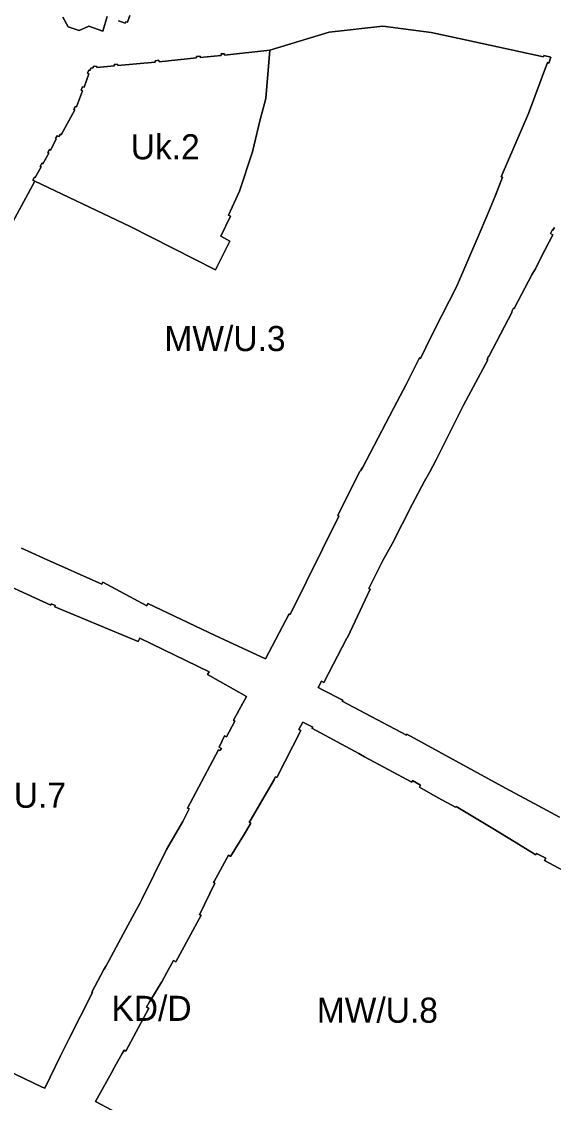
# Model space of a CAD drawing. Extents: x 7423367 to 7424726, y 5546744 to 5548391.
# Drawn here: x 7424088.2 to 7424194.2, y 5547952.8 to 5548168.2 of the extents above; entities that cross this region are included whole.
import ezdxf

# ---------------------------------------------------------------- set-up
doc = ezdxf.new("R2010")
doc.units = 0
doc.layers.add('linie_rozgraniczajace', color=7, linetype='Continuous')
doc.layers.add('oznaczenia_przeznaczen', color=7, linetype='Continuous')

msp = doc.modelspace()

# ---------------------------------------------------------------- linework, layer by layer
at = {"layer": 'linie_rozgraniczajace'}
for points in [[(7424105.26, 5548169.29), (7424104.4, 5548166.36), (7424101.64, 5548167.35), (7424099.67, 5548166.47), (7424097.5, 5548167.2), (7424096.42, 5548169.13)], [(7424096.42, 5548169.13), (7424097.5, 5548167.2), (7424099.67, 5548166.47), (7424101.64, 5548167.35), (7424104.4, 5548166.36), (7424105.26, 5548169.29)], [(7424109.76, 5548169.49), (7424109.3, 5548168.1), (7424108.95, 5548168.19), (7424108.86, 5548167.92), (7424107.5, 5548168.39)], [(7424107.5, 5548168.39), (7424108.86, 5548167.92), (7424108.95, 5548168.19), (7424109.3, 5548168.1), (7424109.76, 5548169.49)], [(7424084.67, 5548124.99), (7424090.84, 5548136.42), (7424109.83, 5548127.39), (7424126.83, 5548118.73), (7424129.73, 5548124.48), (7424127.91, 5548125.47), (7424129.81, 5548129.49), (7424129.45, 5548129.67), (7424131.65, 5548134.44), (7424134.22, 5548142.26), (7424134.55, 5548143.68), (7424135.66, 5548148.46), (7424136.87, 5548152.88), (7424137.67, 5548162.53), (7424149.49, 5548166.12), (7424160.16, 5548167.34), (7424169.79, 5548166.09), (7424175.42, 5548164.85), (7424192.21, 5548161.19), (7424192.27, 5548161.46), (7424193.68, 5548161.14), (7424193.23, 5548159.97), (7424193.01, 5548160.08), (7424189.17, 5548149.89), (7424183.78, 5548137.32), (7424184.04, 5548137.2), (7424182.59, 5548133.44), (7424180.88, 5548129.44), (7424179.35, 5548125.87), (7424174.83, 5548115.34), (7424171.94, 5548109.63), (7424169.76, 5548105.34), (7424167.69, 5548101.09), (7424167.49, 5548101.19), (7424165.03, 5548096.29), (7424164.85, 5548095.93), (7424163.04, 5548092.53), (7424156.18, 5548079.43), (7424155.73, 5548078.7), (7424155.55, 5548078.51), (7424151.21, 5548069.77), (7424151.39, 5548069.66), (7424141.7, 5548050.08), (7424141.5, 5548050.17), (7424136.82, 5548041.22), (7424126.76, 5548045.87), (7424113.37, 5548052.24), (7424113.16, 5548051.79), (7424104.39, 5548056.51), (7424104.17, 5548056.11), (7424092.55, 5548061.3), (7424090.24, 5548062.32), (7424088.17, 5548063.25)], [(7424088.17, 5548063.25), (7424090.24, 5548062.32), (7424092.55, 5548061.3), (7424104.17, 5548056.11), (7424104.39, 5548056.51), (7424113.16, 5548051.79), (7424113.37, 5548052.24), (7424126.76, 5548045.87), (7424136.82, 5548041.22), (7424141.5, 5548050.17), (7424141.7, 5548050.08), (7424151.39, 5548069.66), (7424151.21, 5548069.77), (7424155.55, 5548078.51), (7424155.73, 5548078.7), (7424156.18, 5548079.43), (7424163.04, 5548092.53), (7424164.85, 5548095.93), (7424165.03, 5548096.29), (7424167.49, 5548101.19), (7424167.69, 5548101.09), (7424169.76, 5548105.34), (7424171.94, 5548109.63), (7424174.83, 5548115.34), (7424179.35, 5548125.87), (7424180.88, 5548129.44), (7424182.59, 5548133.44), (7424184.04, 5548137.2), (7424183.78, 5548137.32), (7424189.17, 5548149.89), (7424193.01, 5548160.08), (7424193.23, 5548159.97), (7424193.68, 5548161.14), (7424192.27, 5548161.46), (7424192.21, 5548161.19), (7424175.42, 5548164.85), (7424169.79, 5548166.09), (7424160.16, 5548167.34), (7424149.49, 5548166.12), (7424137.67, 5548162.53), (7424128.64, 5548161.54), (7424128.63, 5548161.82), (7424127.96, 5548161.79), (7424127.94, 5548161.51), (7424123.79, 5548161.07), (7424123.77, 5548161.35), (7424123.09, 5548161.31), (7424123.08, 5548161.03), (7424115.62, 5548160.25), (7424115.54, 5548160.54), (7424114.84, 5548160.45), (7424114.82, 5548160.18), (7424107.37, 5548159.51), (7424107.34, 5548159.77), (7424106.67, 5548159.7), (7424106.7, 5548159.43), (7424103.2, 5548159.08), (7424103.16, 5548159.37), (7424102.45, 5548159.3), (7424102.48, 5548159.02), (7424102.02, 5548158.95), (7424101.88, 5548158.55), (7424101.58, 5548158.57), (7424101.36, 5548157.98), (7424101.6, 5548157.84), (7424100.66, 5548155.14), (7424100.35, 5548155.26), (7424100.11, 5548154.57), (7424100.33, 5548154.46), (7424100.14, 5548153.92), (7424099.17, 5548151.23), (7424098.9, 5548151.34), (7424098.6, 5548150.68), (7424098.79, 5548150.64), (7424096.12, 5548145.7), (7424095.92, 5548145.78), (7424095.68, 5548145.34), (7424095.31, 5548145.5), (7424094.96, 5548144.93), (7424095.13, 5548144.83), (7424093.98, 5548142.62), (7424093.8, 5548142.72), (7424093.45, 5548142.14), (7424093.61, 5548142.04), (7424092.44, 5548139.91), (7424092.27, 5548140), (7424091.93, 5548139.38), (7424092.1, 5548139.29), (7424090.91, 5548137.17), (7424090.76, 5548137.25), (7424090.43, 5548136.65), (7424090.84, 5548136.42), (7424084.67, 5548124.99)], [(7424195.36, 5548009.65), (7424191.2, 5548011.91), (7424184.64, 5548015.43), (7424164.97, 5548026.2), (7424164.89, 5548026.04), (7424152.1, 5548032.8), (7424152.18, 5548032.96), (7424148.13, 5548035.03), (7424147.33, 5548035.5), (7424147.98, 5548036.74), (7424148.4, 5548036.52), (7424153.04, 5548045.33), (7424153.12, 5548045.49), (7424157.63, 5548055.14), (7424157.4, 5548055.27), (7424158.82, 5548058.18), (7424160.2, 5548060.81), (7424162.06, 5548064.16), (7424166.05, 5548071.97), (7424168.46, 5548076.61), (7424169.46, 5548078.39), (7424170.8, 5548080.86), (7424176.23, 5548091.76), (7424181.11, 5548100.84), (7424180.94, 5548100.91), (7424181.25, 5548101.55), (7424181.33, 5548101.51), (7424185.96, 5548110.41), (7424185.89, 5548110.45), (7424186.23, 5548111.09), (7424186.32, 5548111.05), (7424189.95, 5548117.93), (7424190.57, 5548118.95), (7424191.81, 5548121.39), (7424194.07, 5548125.77), (7424193.58, 5548126.03), (7424193.9, 5548126.67), (7424194.01, 5548126.61), (7424194.39, 5548127.21)], [(7424194.39, 5548127.21), (7424194.01, 5548126.61), (7424193.9, 5548126.67), (7424193.58, 5548126.03), (7424194.07, 5548125.77), (7424191.81, 5548121.39), (7424190.57, 5548118.95), (7424189.95, 5548117.93), (7424186.32, 5548111.05), (7424186.23, 5548111.09), (7424185.89, 5548110.45), (7424185.96, 5548110.41), (7424181.33, 5548101.51), (7424181.25, 5548101.55), (7424180.94, 5548100.91), (7424181.11, 5548100.84), (7424176.23, 5548091.76), (7424170.8, 5548080.86), (7424169.46, 5548078.39), (7424168.46, 5548076.61), (7424166.05, 5548071.97), (7424162.06, 5548064.16), (7424160.2, 5548060.81), (7424158.82, 5548058.18), (7424157.4, 5548055.27), (7424157.63, 5548055.14), (7424153.12, 5548045.49), (7424153.04, 5548045.33), (7424148.4, 5548036.52), (7424147.98, 5548036.74), (7424147.33, 5548035.5), (7424148.13, 5548035.03), (7424152.18, 5548032.96), (7424152.1, 5548032.8), (7424164.89, 5548026.04), (7424164.97, 5548026.2), (7424184.64, 5548015.43), (7424191.2, 5548011.91), (7424195.36, 5548009.65)], [(7424067.71, 5548063.98), (7424089.25, 5548054.14), (7424094.01, 5548051.92), (7424094.13, 5548052.19), (7424094.93, 5548051.86), (7424094.83, 5548051.6), (7424111.44, 5548044.71), (7424111.76, 5548045.34), (7424125.57, 5548038.63), (7424125.27, 5548038.07), (7424133.02, 5548033.73), (7424130.41, 5548029.03), (7424130.7, 5548028.8), (7424129.06, 5548025.66), (7424128.67, 5548025.87), (7424127.58, 5548023.59), (7424128.01, 5548023.35), (7424127.74, 5548022.92), (7424127.43, 5548023.06), (7424121.29, 5548011.47), (7424121.61, 5548011.32), (7424121.48, 5548011.04), (7424120.31, 5548008.8), (7424117.11, 5548003.2), (7424112.18, 5547993.28), (7424111.83, 5547992.61), (7424110.71, 5547990.55), (7424110.31, 5547989.78), (7424107.99, 5547985.5), (7424107.52, 5547984.64), (7424105.05, 5547980.04), (7424104.6, 5547979.3), (7424102.19, 5547974.81), (7424102.31, 5547974.74), (7424097.62, 5547965.38), (7424095.94, 5547962.06), (7424092.85, 5547955.66), (7424092.48, 5547955.79), (7424092.32, 5547955.87), (7424079.83, 5547961.85)], [(7424079.83, 5547961.85), (7424092.32, 5547955.87), (7424092.48, 5547955.79), (7424092.85, 5547955.66), (7424095.94, 5547962.06), (7424097.62, 5547965.38), (7424102.31, 5547974.74), (7424102.19, 5547974.81), (7424104.6, 5547979.3), (7424105.05, 5547980.04), (7424107.52, 5547984.64), (7424107.99, 5547985.5), (7424110.31, 5547989.78), (7424110.71, 5547990.55), (7424111.83, 5547992.61), (7424112.18, 5547993.28), (7424117.11, 5548003.2), (7424120.31, 5548008.8), (7424121.48, 5548011.04), (7424121.61, 5548011.32), (7424121.29, 5548011.47), (7424127.43, 5548023.06), (7424127.74, 5548022.92), (7424128.01, 5548023.35), (7424127.58, 5548023.59), (7424128.67, 5548025.87), (7424129.06, 5548025.66), (7424130.7, 5548028.8), (7424130.41, 5548029.03), (7424133.02, 5548033.73), (7424125.27, 5548038.07), (7424125.57, 5548038.63), (7424111.76, 5548045.34), (7424111.44, 5548044.71), (7424094.83, 5548051.6), (7424094.93, 5548051.86), (7424094.13, 5548052.19), (7424094.01, 5548051.92), (7424089.25, 5548054.14), (7424067.71, 5548063.98)], [(7424112.68, 5547947.82), (7424102.94, 5547953.02), (7424103.91, 5547954.79), (7424106.11, 5547958.71), (7424106.71, 5547959.8), (7424108.24, 5547962.55), (7424108.62, 5547963.22), (7424108.95, 5547963.04), (7424113.55, 5547971.57), (7424113.09, 5547971.82), (7424113.69, 5547972.83), (7424114.47, 5547974.11), (7424115.88, 5547976.41), (7424116.15, 5547976.84), (7424117.18, 5547978.71), (7424118.48, 5547981.06), (7424118.94, 5547980.83), (7424123.96, 5547990.1), (7424123.68, 5547990.22), (7424126.7, 5547996.53), (7424126.47, 5547996.62), (7424126.58, 5547996.82), (7424129.43, 5548002.1), (7424129.84, 5548001.84), (7424132.4, 5548006.03), (7424133.87, 5548008.45), (7424133.56, 5548008.65), (7424133.74, 5548008.95), (7424138.63, 5548017.21), (7424138.56, 5548017.25), (7424138.81, 5548017.7), (7424139.06, 5548017.57), (7424143.84, 5548026.97), (7424143.47, 5548027.17), (7424144.23, 5548028.61), (7424146.21, 5548027.62), (7424146.05, 5548027.37), (7424155.38, 5548022.33), (7424156.54, 5548021.7), (7424165.93, 5548016.63), (7424166.11, 5548016.96), (7424167.67, 5548016.05), (7424167.48, 5548015.65), (7424170.17, 5548014.13), (7424171.93, 5548013.14), (7424174.69, 5548011.64), (7424174.82, 5548011.81), (7424181.77, 5548007.6), (7424185.17, 5548005.56), (7424190.64, 5548002.15), (7424190.79, 5548002.43), (7424192.65, 5548001.47), (7424192.42, 5548001.04), (7424211.72, 5547990.69)], [(7424211.72, 5547990.69), (7424192.42, 5548001.04), (7424192.65, 5548001.47), (7424190.79, 5548002.43), (7424190.64, 5548002.15), (7424185.17, 5548005.56), (7424181.77, 5548007.6), (7424174.82, 5548011.81), (7424174.69, 5548011.64), (7424171.93, 5548013.14), (7424170.17, 5548014.13), (7424167.48, 5548015.65), (7424167.67, 5548016.05), (7424166.11, 5548016.96), (7424165.93, 5548016.63), (7424156.54, 5548021.7), (7424155.38, 5548022.33), (7424146.05, 5548027.37), (7424146.21, 5548027.62), (7424144.23, 5548028.61), (7424143.47, 5548027.17), (7424143.84, 5548026.97), (7424139.06, 5548017.57), (7424138.81, 5548017.7), (7424138.56, 5548017.25), (7424138.63, 5548017.21), (7424133.74, 5548008.95), (7424133.56, 5548008.65), (7424133.87, 5548008.45), (7424132.4, 5548006.03), (7424129.84, 5548001.84), (7424129.43, 5548002.1), (7424126.58, 5547996.82), (7424126.47, 5547996.62), (7424126.7, 5547996.53), (7424123.68, 5547990.22), (7424123.96, 5547990.1), (7424118.94, 5547980.83), (7424118.48, 5547981.06), (7424117.18, 5547978.71), (7424116.15, 5547976.84), (7424115.88, 5547976.41), (7424114.47, 5547974.11), (7424113.69, 5547972.83), (7424113.09, 5547971.82), (7424113.55, 5547971.57), (7424108.95, 5547963.04), (7424108.62, 5547963.22), (7424108.24, 5547962.55), (7424106.71, 5547959.8), (7424106.11, 5547958.71), (7424103.91, 5547954.79), (7424102.94, 5547953.02), (7424112.68, 5547947.82)]]:
    msp.add_lwpolyline(points, dxfattribs=at)
msp.add_lwpolyline([(7424090.43, 5548136.65), (7424090.76, 5548137.25), (7424090.91, 5548137.17), (7424092.1, 5548139.29), (7424091.93, 5548139.38), (7424092.27, 5548140), (7424092.44, 5548139.91), (7424093.61, 5548142.04), (7424093.45, 5548142.14), (7424093.8, 5548142.72), (7424093.98, 5548142.62), (7424095.13, 5548144.83), (7424094.96, 5548144.93), (7424095.31, 5548145.5), (7424095.68, 5548145.34), (7424095.92, 5548145.78), (7424096.12, 5548145.7), (7424098.79, 5548150.64), (7424098.6, 5548150.68), (7424098.9, 5548151.34), (7424099.17, 5548151.23), (7424100.14, 5548153.92), (7424100.33, 5548154.46), (7424100.11, 5548154.57), (7424100.35, 5548155.26), (7424100.66, 5548155.14), (7424101.6, 5548157.84), (7424101.36, 5548157.98), (7424101.58, 5548158.57), (7424101.88, 5548158.55), (7424102.02, 5548158.95), (7424102.48, 5548159.02), (7424102.45, 5548159.3), (7424103.16, 5548159.37), (7424103.2, 5548159.08), (7424106.7, 5548159.43), (7424106.67, 5548159.7), (7424107.34, 5548159.77), (7424107.37, 5548159.51), (7424114.82, 5548160.18), (7424114.84, 5548160.45), (7424115.54, 5548160.54), (7424115.62, 5548160.25), (7424123.08, 5548161.03), (7424123.09, 5548161.31), (7424123.77, 5548161.35), (7424123.79, 5548161.07), (7424127.94, 5548161.51), (7424127.96, 5548161.79), (7424128.63, 5548161.82), (7424128.64, 5548161.54), (7424137.67, 5548162.53), (7424136.87, 5548152.88), (7424135.66, 5548148.46), (7424134.55, 5548143.68), (7424134.22, 5548142.26), (7424131.65, 5548134.44), (7424129.45, 5548129.67), (7424129.81, 5548129.49), (7424127.91, 5548125.47), (7424129.73, 5548124.48), (7424126.83, 5548118.73), (7424109.83, 5548127.39), (7424090.84, 5548136.42)], close=True, dxfattribs=at)

# ---------------------------------------------------------------- texts
at = {"layer": 'oznaczenia_przeznaczen'}
for s, p in [('Uk.2', (7424109.96, 5548140.79)), ('MW/U.3', (7424116.66, 5548102.57)), ('MW/U.7', (7424072.93, 5548011.53)), ('KD/D', (7424106.11, 5547969.06)), ('MW/U.8', (7424147.02, 5547968.69))]:
    msp.add_text(s, height=5, dxfattribs=at).set_placement(p)

doc.saveas('drawing.dxf')
